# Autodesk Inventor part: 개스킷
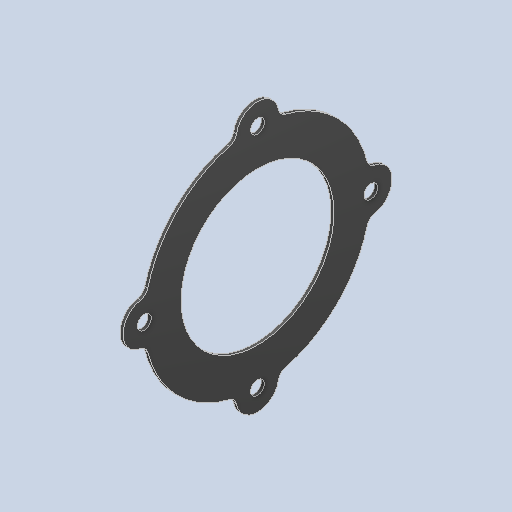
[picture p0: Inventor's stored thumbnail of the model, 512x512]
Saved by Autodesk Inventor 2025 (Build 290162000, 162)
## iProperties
Created: 2024-08
Part Number: 개스킷
Material: 황동, 연질 노란색
Document SubType Name: Modeling
Designer: SAMSUNG
Density: 8.47 g/cm^3
Appearance: 기본값
Sending System: Autodesk Inventor 2025
Preprocessor: ST-DEVELOPER v20
Author: jhkim
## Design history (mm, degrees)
feature "솔리드2"
node "솔리드1"
